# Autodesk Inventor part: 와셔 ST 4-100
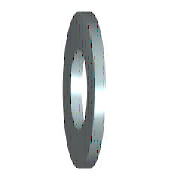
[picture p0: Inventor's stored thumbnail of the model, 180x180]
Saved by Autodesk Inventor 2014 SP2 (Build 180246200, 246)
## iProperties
IsCustomPart: 0
Created: 2012-02
Part Number: 와셔 ST 4-100
Material: 강철, 연강
Description: 평면 와셔 - 일반 시리즈 - 제품 등급 C
Document SubType Name: Modeling
Standard: ISO 7091
Designer: mduedu
Standard Revision: Second edition 2000-06-01
Standards Organization: ISO
Language: ko-KR
Size Designation: ST 4 - 100 HV
Categories: <MemberInstance><Categories><Category DisplayName="조임쇠" InternalName="e4da775c-781d-43d5-af7c-5136215cf5a6" Mnemonic="FSTN"><Category DisplayName="와셔" InternalN
Density: 7.86 g/cm^3
Mass: 0.492315 g
Surface Area: 1.70824 cm^2
Volume: 0.0626355 cm^3
Appearance: 파란색 - 벽 페인트 - 광택
Author: mduedu
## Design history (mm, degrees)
sketch "스케치"
  geometry: C1 r 5 at (0, 0); C2 r 2.25 at (0, 0); 1 further point
  constraints: 2 centre point, 2 coincident
  dimensions: "d0" = 4.5 diameter of C2 (= SD1); "d1" = 10 diameter of C1 (= SD2)
extrude "본체" new body sketch "스케치" distance "d2" = 1 (= SD); taper "d3" = 0 deg
workaxis "Work Axis1"
workplane "Work Plane1"
body "Solid1"
other parameters: "SD1" = 4.5 [user parameter; used in 1 equation term], "SD2" = 10 [user parameter; used in 1 equation term], "SD" = 1 [user parameter; used in 1 equation term], "d4" = 0, "d5" = 0, "d6" = 0, "d7" = 0, "NND" = 4 [user parameter]
